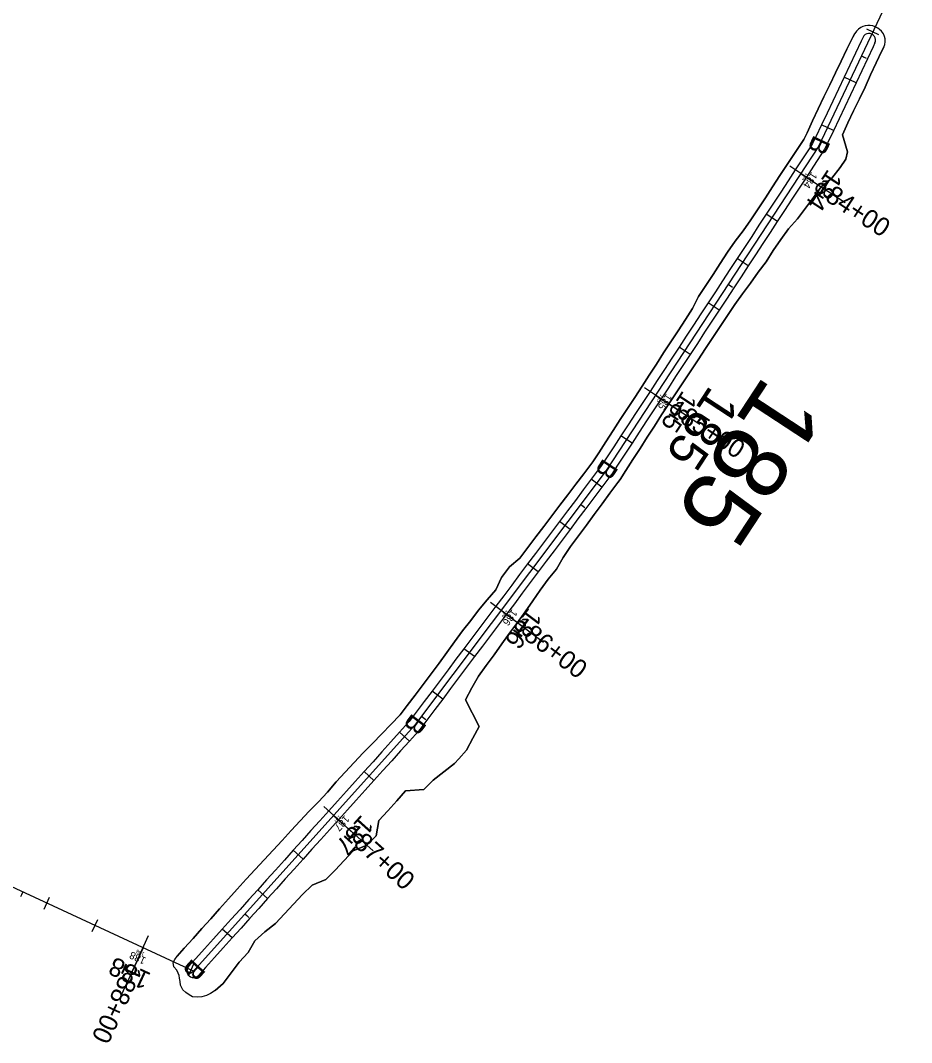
# Model space of a CAD drawing. Extents: x 1823824 to 1861612, y 706975 to 726130.
# Drawn here: x 1826320.7 to 1826656.9, y 713131.9 to 713517.6 of the extents above; entities that cross this region are included whole.
import ezdxf

# ---------------------------------------------------------------- set-up
doc = ezdxf.new("R2010")
doc.units = 0
for name, color, linetype in [('DR_X_Flood_Boundary', 7, 'Continuous'), ('GE_X_CL_10', 7, 'Continuous'), ('GE_X_CL_100', 7, 'Continuous'), ('GE_X_CL_20', 7, 'Continuous'), ('GE_X_CL_200', 7, 'Continuous'), ('GE_X_CL_50', 7, 'Continuous'), ('SC_Scratch1', 7, 'Continuous'), ('SC_Scratch5', 7, 'Continuous'), ('SC_Scratch6', 7, 'Continuous')]:
    doc.layers.add(name, color=color, linetype=linetype)

msp = doc.modelspace()

# ---------------------------------------------------------------- linework, layer by layer
at = {"layer": 'DR_X_Flood_Boundary'}
for p, q in [((1826656.88, 713544.06), (1826621.8, 713470.05)), ((1826621.8, 713470.05), (1826541.65, 713347.77)), ((1826541.65, 713347.77), (1826469.32, 713251.5)), ((1826469.32, 713251.5), (1826385.95, 713158.86)), ((1826385.95, 713158.86), (1826309.82, 713194.11))]:
    msp.add_line(p, q, dxfattribs=at)
at = {"layer": 'GE_X_CL_10'}
for p, q in [((1826637.98, 713504.2), (1826638.89, 713503.77)), ((1826615.11, 713459.83), (1826615.94, 713459.29)), ((1826587.7, 713418.02), (1826588.53, 713417.47)), ((1826560.29, 713376.2), (1826561.12, 713375.65)), ((1826532.04, 713334.97), (1826532.84, 713334.37)), ((1826502, 713295), (1826502.8, 713294.4)), ((1826471.97, 713255.02), (1826472.77, 713254.42)), ((1826438.82, 713217.61), (1826439.57, 713216.94)), ((1826321.55, 713188.67), (1826321.13, 713187.77)), ((1826405.37, 713180.45), (1826406.12, 713179.78)), ((1826366.93, 713167.67), (1826366.51, 713166.76))]:
    msp.add_line(p, q, dxfattribs=at)
at = {"layer": 'GE_X_CL_100'}
for p, q in [((1826615.11, 713459.83), (1826623.47, 713454.35)), ((1826560.29, 713376.2), (1826568.65, 713370.72)), ((1826502, 713295), (1826510, 713288.99)), ((1826438.82, 713217.61), (1826446.26, 713210.92)), ((1826366.93, 713167.67), (1826362.72, 713158.59))]:
    msp.add_line(p, q, dxfattribs=at)
at = {"layer": 'GE_X_CL_20'}
for p, q in [((1826637.98, 713504.2), (1826639.79, 713503.34)), ((1826615.11, 713459.83), (1826616.78, 713458.74)), ((1826587.7, 713418.02), (1826589.37, 713416.92)), ((1826560.29, 713376.2), (1826561.96, 713375.1)), ((1826532.04, 713334.97), (1826533.64, 713333.77)), ((1826502, 713295), (1826503.6, 713293.8)), ((1826471.97, 713255.02), (1826473.57, 713253.82)), ((1826438.82, 713217.61), (1826440.31, 713216.27)), ((1826321.55, 713188.67), (1826320.71, 713186.86)), ((1826405.37, 713180.45), (1826406.86, 713179.11)), ((1826366.93, 713167.67), (1826366.09, 713165.85))]:
    msp.add_line(p, q, dxfattribs=at)
at = {"layer": 'GE_X_CL_200'}
for p, q in [((1826615.11, 713459.83), (1826631.84, 713448.87)), ((1826560.29, 713376.2), (1826577.01, 713365.24)), ((1826502, 713295), (1826517.99, 713282.98)), ((1826438.82, 713217.61), (1826453.69, 713204.23)), ((1826366.93, 713167.67), (1826358.52, 713149.52))]:
    msp.add_line(p, q, dxfattribs=at)
at = {"layer": 'GE_X_CL_50'}
for p, q in [((1826615.11, 713459.83), (1826619.29, 713457.09)), ((1826560.29, 713376.2), (1826564.47, 713373.46)), ((1826502, 713295), (1826506, 713291.99)), ((1826438.82, 713217.61), (1826442.54, 713214.27)), ((1826366.93, 713167.67), (1826364.82, 713163.13))]:
    msp.add_line(p, q, dxfattribs=at)
at = {"layer": 'SC_Scratch1'}
for points in [[(1826646.43, 713507.53), (1826646.8, 713508.49), (1826646.98, 713509.5), (1826646.95, 713510.62), (1826646.71, 713511.6), (1826646.24, 713512.61), (1826645.53, 713513.53), (1826644.84, 713514.19), (1826644.12, 713514.75), (1826643.19, 713515.23), (1826642.31, 713515.53), (1826641.28, 713515.7), (1826640.43, 713515.71), (1826639.43, 713515.57), (1826638.55, 713515.3), (1826637.73, 713514.92), (1826636.84, 713514.32), (1826636.07, 713513.57), (1826635.49, 713512.71)], [(1826379.79, 713164.46), (1826382.46, 713167.44), (1826385.79, 713171.16), (1826389.13, 713174.89), (1826392.46, 713178.61), (1826395.8, 713182.34), (1826399.12, 713186.07), (1826402.46, 713189.79), (1826405.83, 713193.49), (1826409.2, 713197.18), (1826412.61, 713200.84), (1826416, 713204.51), (1826419.4, 713208.18), (1826422.8, 713211.85), (1826426.2, 713215.52), (1826429.64, 713219.15), (1826433.1, 713222.76), (1826436.52, 713226.41), (1826439.78, 713230.2), (1826443.18, 713233.87), (1826446.56, 713237.55), (1826449.96, 713241.22), (1826453.51, 713244.75), (1826456.96, 713248.37), (1826460.45, 713251.96), (1826463.91, 713255.58), (1826463.93, 713255.55), (1826466.6, 713259.05), (1826469.65, 713263.02), (1826472.6, 713267.05), (1826475.58, 713271.07), (1826478.6, 713275.06), (1826481.56, 713279.09), (1826484.47, 713283.15), (1826487.42, 713287.19), (1826490.55, 713291.09), (1826493.54, 713295.1), (1826496.7, 713298.98), (1826500.05, 713302.72), (1826502.2, 713307.36), (1826505.19, 713311.37), (1826509.07, 713314.7), (1826512.09, 713318.69), (1826515.1, 713322.68), (1826518.11, 713326.67), (1826521.14, 713330.65), (1826524.17, 713334.63), (1826527.21, 713338.6), (1826530.26, 713342.56), (1826533.26, 713346.56), (1826536.28, 713350.55), (1826536.67, 713351.04), (1826538.83, 713354.39), (1826541.53, 713358.6), (1826544.25, 713362.8), (1826546.96, 713367), (1826549.71, 713371.17), (1826552.46, 713375.35), (1826555.2, 713379.53), (1826557.92, 713383.73), (1826560.62, 713387.94), (1826563.32, 713392.15), (1826566.04, 713396.34), (1826568.82, 713400.5), (1826571.54, 713404.69), (1826574.26, 713408.89), (1826576.52, 713413.39), (1826579.25, 713417.57), (1826581.99, 713421.76), (1826584.72, 713425.94), (1826587.48, 713430.11), (1826590.27, 713434.26), (1826593.38, 713438.21), (1826596.22, 713442.32), (1826598.97, 713446.5), (1826601.71, 713450.68), (1826604.46, 713454.85), (1826607.22, 713459.03), (1826609.89, 713463.25), (1826612.67, 713467.41), (1826615.46, 713471.56), (1826616.27, 713472.67), (1826617.45, 713475.19), (1826619.54, 713479.74), (1826621.65, 713484.27), (1826623.83, 713488.77), (1826626, 713493.28), (1826628.15, 713497.79), (1826630.34, 713502.29), (1826632.52, 713506.78), (1826634.69, 713511.29), (1826635.49, 713512.71)], [(1826635.49, 713512.71), (1826634.69, 713511.29), (1826632.52, 713506.78), (1826630.34, 713502.29), (1826628.15, 713497.79), (1826626, 713493.28), (1826623.83, 713488.77), (1826621.65, 713484.27), (1826619.54, 713479.74), (1826617.45, 713475.19), (1826616.27, 713472.67), (1826615.46, 713471.56), (1826612.67, 713467.41), (1826609.89, 713463.25), (1826607.22, 713459.03), (1826604.46, 713454.85), (1826601.71, 713450.68), (1826598.97, 713446.5), (1826596.22, 713442.32), (1826593.38, 713438.21), (1826590.27, 713434.26), (1826587.48, 713430.11), (1826584.72, 713425.94), (1826581.99, 713421.76), (1826579.25, 713417.57), (1826576.52, 713413.39), (1826574.26, 713408.89), (1826571.54, 713404.69), (1826568.82, 713400.5), (1826566.04, 713396.34), (1826563.32, 713392.15), (1826560.62, 713387.94), (1826557.92, 713383.73), (1826555.2, 713379.53), (1826552.46, 713375.35), (1826549.71, 713371.17), (1826546.96, 713367), (1826544.25, 713362.8), (1826541.53, 713358.6), (1826538.83, 713354.39), (1826536.67, 713351.04), (1826536.28, 713350.55), (1826533.26, 713346.56), (1826530.26, 713342.56), (1826527.21, 713338.6), (1826524.17, 713334.63), (1826521.14, 713330.65), (1826518.11, 713326.67), (1826515.1, 713322.68), (1826512.09, 713318.69), (1826509.07, 713314.7), (1826505.19, 713311.37), (1826502.2, 713307.36), (1826500.05, 713302.72), (1826496.7, 713298.98), (1826493.54, 713295.1), (1826490.55, 713291.09), (1826487.42, 713287.19), (1826484.47, 713283.15), (1826481.56, 713279.09), (1826478.6, 713275.06), (1826475.58, 713271.07), (1826472.6, 713267.05), (1826469.65, 713263.02), (1826466.6, 713259.05), (1826463.93, 713255.55), (1826463.91, 713255.58), (1826460.45, 713251.96), (1826456.96, 713248.37), (1826453.51, 713244.75), (1826449.96, 713241.22), (1826446.56, 713237.55), (1826443.18, 713233.87), (1826439.78, 713230.2), (1826436.52, 713226.41), (1826433.1, 713222.76), (1826429.64, 713219.15), (1826426.2, 713215.52), (1826422.8, 713211.85), (1826419.4, 713208.18), (1826416, 713204.51), (1826412.61, 713200.84), (1826409.2, 713197.18), (1826405.83, 713193.49), (1826402.46, 713189.79), (1826399.12, 713186.07), (1826395.8, 713182.34), (1826392.46, 713178.61), (1826389.13, 713174.89), (1826385.79, 713171.16), (1826382.46, 713167.44), (1826379.79, 713164.46)], [(1826638.56, 713511.26), (1826637.87, 713509.78), (1826635.72, 713505.27), (1826633.58, 713500.75), (1826631.44, 713496.23), (1826629.3, 713491.71), (1826627.16, 713487.19), (1826625.02, 713482.67), (1826622.88, 713478.16), (1826620.74, 713473.64), (1826619.54, 713471.12), (1826618.5, 713469.57), (1826615.76, 713465.39), (1826613.02, 713461.2), (1826610.28, 713457.02), (1826607.53, 713452.84), (1826604.79, 713448.66), (1826602.05, 713444.48), (1826599.31, 713440.3), (1826596.57, 713436.11), (1826593.83, 713431.93), (1826591.09, 713427.75), (1826588.35, 713423.57), (1826585.61, 713419.39), (1826582.87, 713415.2), (1826580.12, 713411.02), (1826577.38, 713406.84), (1826574.64, 713402.66), (1826571.9, 713398.48), (1826569.16, 713394.3), (1826566.42, 713390.11), (1826563.68, 713385.93), (1826560.94, 713381.75), (1826558.2, 713377.57), (1826555.46, 713373.39), (1826552.71, 713369.21), (1826549.97, 713365.02), (1826547.23, 713360.84), (1826544.49, 713356.66), (1826541.75, 713352.48), (1826539.56, 713349.14), (1826539.05, 713348.47), (1826536.05, 713344.47), (1826533.04, 713340.47), (1826530.04, 713336.47), (1826527.04, 713332.48), (1826524.03, 713328.48), (1826521.03, 713324.48), (1826518.03, 713320.48), (1826515.02, 713316.49), (1826512.02, 713312.49), (1826509.02, 713308.49), (1826506.01, 713304.49), (1826503.01, 713300.5), (1826500.01, 713296.5), (1826497, 713292.5), (1826494, 713288.5), (1826491, 713284.51), (1826487.99, 713280.51), (1826484.99, 713276.51), (1826481.99, 713272.51), (1826478.98, 713268.52), (1826475.98, 713264.52), (1826472.98, 713260.52), (1826469.97, 713256.52), (1826467.32, 713253), (1826467.07, 713252.73), (1826463.72, 713249.01), (1826460.38, 713245.3), (1826457.03, 713241.58), (1826453.69, 713237.86), (1826450.34, 713234.15), (1826447, 713230.43), (1826443.65, 713226.71), (1826440.31, 713223), (1826436.96, 713219.28), (1826433.62, 713215.57), (1826430.27, 713211.85), (1826426.93, 713208.13), (1826423.58, 713204.42), (1826420.24, 713200.7), (1826416.89, 713196.98), (1826413.55, 713193.27), (1826410.2, 713189.55), (1826406.86, 713185.83), (1826403.51, 713182.12), (1826400.17, 713178.4), (1826396.82, 713174.69), (1826393.48, 713170.97), (1826390.14, 713167.25), (1826386.79, 713163.54), (1826384.11, 713160.56)], [(1826643.08, 713509.12), (1826642.38, 713507.64), (1826640.24, 713503.12), (1826638.1, 713498.61), (1826635.96, 713494.09), (1826633.82, 713489.57), (1826631.68, 713485.05), (1826629.54, 713480.53), (1826627.4, 713476.01), (1826625.26, 713471.5), (1826624.06, 713468.97), (1826622.68, 713466.83), (1826619.94, 713462.64), (1826617.2, 713458.46), (1826614.46, 713454.28), (1826611.72, 713450.1), (1826608.98, 713445.92), (1826606.23, 713441.74), (1826603.49, 713437.55), (1826600.75, 713433.37), (1826598.01, 713429.19), (1826595.27, 713425.01), (1826592.53, 713420.83), (1826589.79, 713416.65), (1826587.05, 713412.46), (1826584.31, 713408.28), (1826581.57, 713404.1), (1826578.82, 713399.92), (1826576.08, 713395.74), (1826573.34, 713391.56), (1826570.6, 713387.37), (1826567.86, 713383.19), (1826565.12, 713379.01), (1826562.38, 713374.83), (1826559.64, 713370.65), (1826556.9, 713366.46), (1826554.15, 713362.28), (1826551.41, 713358.1), (1826548.67, 713353.92), (1826545.93, 713349.74), (1826543.74, 713346.4), (1826543.05, 713345.46), (1826540.04, 713341.46), (1826537.04, 713337.47), (1826534.04, 713333.47), (1826531.03, 713329.47), (1826528.03, 713325.47), (1826525.03, 713321.48), (1826522.02, 713317.48), (1826519.02, 713313.48), (1826516.02, 713309.48), (1826513.01, 713305.49), (1826510.01, 713301.49), (1826507.01, 713297.49), (1826504, 713293.49), (1826501, 713289.5), (1826498, 713285.5), (1826494.99, 713281.5), (1826491.99, 713277.5), (1826488.99, 713273.51), (1826485.98, 713269.51), (1826482.98, 713265.51), (1826479.98, 713261.51), (1826476.97, 713257.52), (1826473.97, 713253.52), (1826471.32, 713250), (1826470.79, 713249.38), (1826467.44, 713245.67), (1826464.1, 713241.95), (1826460.75, 713238.24), (1826457.41, 713234.52), (1826454.06, 713230.8), (1826450.72, 713227.09), (1826447.37, 713223.37), (1826444.03, 713219.65), (1826440.68, 713215.94), (1826437.34, 713212.22), (1826433.99, 713208.5), (1826430.65, 713204.79), (1826427.3, 713201.07), (1826423.96, 713197.36), (1826420.61, 713193.64), (1826417.27, 713189.92), (1826413.92, 713186.21), (1826410.58, 713182.49), (1826407.23, 713178.77), (1826403.89, 713175.06), (1826400.54, 713171.34), (1826397.2, 713167.62), (1826393.85, 713163.91), (1826390.51, 713160.19), (1826387.83, 713157.22)], [(1826394.16, 713151.52), (1826397.17, 713154.2), (1826400.22, 713158.18), (1826403.17, 713162.24), (1826406.58, 713165.91), (1826409.16, 713170.31), (1826412.93, 713173.65), (1826416.93, 713176.77), (1826420.31, 713180.46), (1826423.7, 713184.13), (1826427.1, 713187.79), (1826430.75, 713191.24), (1826435.87, 713193.36), (1826439.38, 713196.93), (1826442.84, 713200.54), (1826446.19, 713204.25), (1826451.35, 713206.34), (1826454.9, 713209.87), (1826455.92, 713215.67), (1826459.32, 713219.34), (1826462.64, 713223.08), (1826465.97, 713226.81), (1826472.84, 713227.36), (1826476.41, 713230.87), (1826480.36, 713234.04), (1826484.4, 713237.13), (1826486.11, 713238.88), (1826489.01, 713242.22), (1826491.4, 713246.68), (1826493.77, 713251.15), (1826488.63, 713261.26), (1826490.97, 713265.76), (1826493.52, 713270.1), (1826496.37, 713274.22), (1826499.34, 713278.24), (1826502.25, 713282.3), (1826505.23, 713286.32), (1826508.16, 713290.37), (1826511.09, 713294.42), (1826513.95, 713298.53), (1826516.79, 713302.65), (1826519.73, 713306.7), (1826522.9, 713310.56), (1826525.38, 713314.95), (1826528.17, 713319.11), (1826531.22, 713323.08), (1826534.2, 713327.09), (1826537.15, 713331.13), (1826540.09, 713335.18), (1826543.07, 713339.19), (1826546.08, 713343.18), (1826546.91, 713344.32), (1826549.02, 713347.71), (1826551.73, 713351.91), (1826554.44, 713356.12), (1826557.14, 713360.32), (1826559.86, 713364.52), (1826562.59, 713368.71), (1826565.35, 713372.88), (1826568.13, 713377.04), (1826570.87, 713381.22), (1826573.6, 713385.41), (1826576.36, 713389.58), (1826579.11, 713393.75), (1826581.89, 713397.91), (1826584.66, 713402.07), (1826587.42, 713406.24), (1826590.19, 713410.4), (1826593.11, 713414.47), (1826596.1, 713418.49), (1826598.98, 713422.58), (1826602.04, 713426.55), (1826604.65, 713430.82), (1826607.53, 713434.91), (1826610.46, 713438.96), (1826613.8, 713442.75), (1826616.86, 713446.73), (1826619.87, 713450.73), (1826622.8, 713454.79), (1826626.83, 713458.13), (1826629.9, 713462.1), (1826632.02, 713465.2), (1826632.66, 713467.99), (1826630.81, 713474.4), (1826632.87, 713478.96), (1826634.96, 713483.5), (1826637.2, 713487.97), (1826639.34, 713492.48), (1826641.38, 713497.05), (1826643.49, 713501.58), (1826645.67, 713506.09), (1826646.43, 713507.53)], [(1826646.43, 713507.53), (1826645.67, 713506.09), (1826643.49, 713501.58), (1826641.38, 713497.05), (1826639.34, 713492.48), (1826637.2, 713487.97), (1826634.96, 713483.5), (1826632.87, 713478.96), (1826630.81, 713474.4), (1826632.66, 713467.99), (1826632.02, 713465.2), (1826629.9, 713462.1), (1826626.83, 713458.13), (1826622.8, 713454.79), (1826619.87, 713450.73), (1826616.86, 713446.73), (1826613.8, 713442.75), (1826610.46, 713438.96), (1826607.53, 713434.91), (1826604.65, 713430.82), (1826602.04, 713426.55), (1826598.98, 713422.58), (1826596.1, 713418.49), (1826593.11, 713414.47), (1826590.19, 713410.4), (1826587.42, 713406.24), (1826584.66, 713402.07), (1826581.89, 713397.91), (1826579.11, 713393.75), (1826576.36, 713389.58), (1826573.6, 713385.41), (1826570.87, 713381.22), (1826568.13, 713377.04), (1826565.35, 713372.88), (1826562.59, 713368.71), (1826559.86, 713364.52), (1826557.14, 713360.32), (1826554.44, 713356.12), (1826551.73, 713351.91), (1826549.02, 713347.71), (1826546.91, 713344.32), (1826546.08, 713343.18), (1826543.07, 713339.19), (1826540.09, 713335.18), (1826537.15, 713331.13), (1826534.2, 713327.09), (1826531.22, 713323.08), (1826528.17, 713319.11), (1826525.38, 713314.95), (1826522.9, 713310.56), (1826519.73, 713306.7), (1826516.79, 713302.65), (1826513.95, 713298.53), (1826511.09, 713294.42), (1826508.16, 713290.37), (1826505.23, 713286.32), (1826502.25, 713282.3), (1826499.34, 713278.24), (1826496.37, 713274.22), (1826493.52, 713270.1), (1826490.97, 713265.76), (1826488.63, 713261.26), (1826493.77, 713251.15), (1826491.4, 713246.68), (1826489.01, 713242.22), (1826486.11, 713238.88), (1826484.4, 713237.13), (1826480.36, 713234.04), (1826476.41, 713230.87), (1826472.84, 713227.36), (1826465.97, 713226.81), (1826462.64, 713223.08), (1826459.32, 713219.34), (1826455.92, 713215.67), (1826454.9, 713209.87), (1826451.35, 713206.34), (1826446.19, 713204.25), (1826442.84, 713200.54), (1826439.38, 713196.93), (1826435.87, 713193.36), (1826430.75, 713191.24), (1826427.1, 713187.79), (1826423.7, 713184.13), (1826420.31, 713180.46), (1826416.93, 713176.77), (1826412.93, 713173.65), (1826409.16, 713170.31), (1826406.58, 713165.91), (1826403.17, 713162.24), (1826400.22, 713158.18), (1826397.17, 713154.2), (1826394.16, 713151.52)], [(1826394.16, 713151.52), (1826392.43, 713150.41), (1826390.92, 713149.66), (1826389.1, 713149.09), (1826387.54, 713148.95), (1826385.64, 713149.18), (1826384.33, 713149.83), (1826383.1, 713150.71), (1826381.96, 713151.74), (1826381.09, 713153.51), (1826380.91, 713154.9), (1826380.71, 713156.16), (1826380.5, 713157.22), (1826380.13, 713157.99), (1826379.64, 713159.16), (1826378.6, 713160.48), (1826378.3, 713162.1), (1826378.88, 713163.24), (1826379.79, 713164.46)]]:
    msp.add_lwpolyline(points, dxfattribs=at)
for centre, start, end in [((1826640.82, 713510.19), 334.6342, 154.6578), ((1826385.97, 713158.89), 137.9963, 318.0162)]:
    msp.add_arc(centre, 2.5, start, end, dxfattribs=at)
at = {"layer": 'SC_Scratch5'}
for points in [[(1826644.53, 713512.16), (1826640.01, 713514.3)], [(1826635.96, 713494.09), (1826631.44, 713496.23)], [(1826627.4, 713476.02), (1826622.88, 713478.16)], [(1826619.29, 713457.09), (1826610.93, 713462.58)], [(1826606.24, 713441.74), (1826602.05, 713444.48)], [(1826595.27, 713425.01), (1826591.09, 713427.75)], [(1826584.31, 713408.28), (1826580.13, 713411.02)], [(1826573.34, 713391.56), (1826569.16, 713394.3)], [(1826564.47, 713373.46), (1826556.11, 713378.94)], [(1826551.41, 713358.1), (1826547.23, 713360.84)], [(1826540.04, 713341.47), (1826536.05, 713344.47)], [(1826528.03, 713325.48), (1826524.03, 713328.48)], [(1826516.02, 713309.49), (1826512.02, 713312.49)], [(1826506, 713291.99), (1826498.01, 713298)], [(1826491.99, 713277.51), (1826487.99, 713280.51)], [(1826479.98, 713261.52), (1826475.98, 713264.52)], [(1826467.44, 713245.67), (1826463.72, 713249.01)], [(1826454.06, 713230.8), (1826450.34, 713234.15)], [(1826442.54, 713214.27), (1826435.11, 713220.96)], [(1826427.3, 713201.07), (1826423.59, 713204.42)], [(1826329.58, 713182.2), (1826331.68, 713186.74)], [(1826413.92, 713186.21), (1826410.21, 713189.55)], [(1826347.73, 713173.8), (1826349.83, 713178.34)], [(1826364.82, 713163.13), (1826369.03, 713172.21)], [(1826400.54, 713171.34), (1826396.83, 713174.69)], [(1826384.02, 713157), (1826386.13, 713161.54)]]:
    msp.add_lwpolyline(points, dxfattribs=at)

# ---------------------------------------------------------------- texts
at = {"layer": 'GE_X_CL_10'}
for s, rotation, p in [('184', 236.7561, (1826617.16, 713460.23)), ('185', 236.7561, (1826562.35, 713376.61)), ('186', 233.0825, (1826504.09, 713295.28)), ('187', 228.0109, (1826440.94, 713217.73)), ('188', 155.1591, (1826367.61, 713165.7))]:
    msp.add_text(s, height=1.4, rotation=rotation, dxfattribs=at).set_placement(p)
at = {"layer": 'GE_X_CL_100'}
msp.add_text('185', height=14, rotation=236.7561, dxfattribs=at).set_placement((1826580.9, 713380.28))
at = {"layer": 'GE_X_CL_20'}
for s, rotation, p in [('184', 236.7561, (1826619.21, 713460.62)), ('185', 236.7561, (1826564.41, 713377.02)), ('186', 233.0825, (1826506.18, 713295.56)), ('187', 228.0109, (1826443.07, 713217.84)), ('188', 155.1591, (1826368.29, 713163.73))]:
    msp.add_text(s, height=2.8, rotation=rotation, dxfattribs=at).set_placement(p)
at = {"layer": 'GE_X_CL_200'}
msp.add_text('185', height=28, rotation=236.7561, dxfattribs=at).set_placement((1826601.51, 713384.36))
at = {"layer": 'GE_X_CL_50'}
for s, rotation, p in [('184', 236.7561, (1826625.37, 713461.81)), ('185', 236.7561, (1826570.59, 713378.24)), ('186', 233.0825, (1826512.44, 713296.4)), ('187', 228.0109, (1826449.43, 713218.18)), ('188', 155.1591, (1826370.33, 713157.83))]:
    msp.add_text(s, height=7, rotation=rotation, dxfattribs=at).set_placement(p)
at = {"layer": 'SC_Scratch5'}
for s, rotation, p in [('184+00', 326.7561, (1826619.46, 713452.8)), ('185+00', 326.7561, (1826564.64, 713369.16)), ('186+00', 323.0825, (1826505.9, 713287.69)), ('187+00', 318.0109, (1826442.06, 713209.99)), ('188+00', 245.1591, (1826360.6, 713162.33))]:
    msp.add_text(s, height=7, rotation=rotation, dxfattribs=at).set_placement(p)
at = {"layer": 'SC_Scratch6'}
for rotation, p in [(244.646, (1826620.14, 713474.71)), (236.7561, (1826540.64, 713352.62)), (233.0825, (1826468.63, 713256.4)), (228.0109, (1826385.69, 713163.81))]:
    msp.add_text('B', height=7, rotation=rotation, dxfattribs=at).set_placement(p)

doc.saveas('drawing.dxf')
